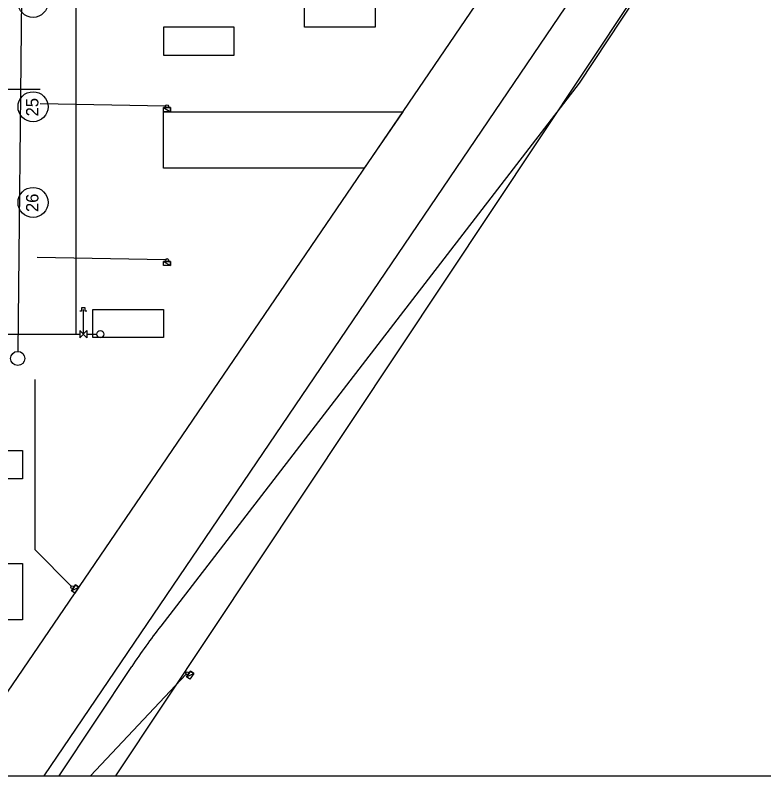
# Model space of a CAD drawing. Extents: x -264031 to -263588, y -1242281 to -1242059.
# Drawn here: x -263792.5 to -263739.4, y -1242281.4 to -1242227.5 of the extents above; entities that cross this region are included whole.
import ezdxf

# ---------------------------------------------------------------- set-up
doc = ezdxf.new("R2010")
doc.units = 0
for name, color, linetype in [('HESCON_OSI_STAVBY_KFA', 7, 'Continuous'), ('KFA_2D_SITUACIA_DSP', 7, 'Continuous'), ('KFA_JESTV_IS_DSP_-_KANAL_SPLASK', 7, 'Continuous'), ('RAM_NA_TLAC_3xA4_1-750', 7, 'Continuous')]:
    doc.layers.add(name, color=color, linetype=linetype)

msp = doc.modelspace()

# ---------------------------------------------------------------- linework, layer by layer
at = {"layer": 'HESCON_OSI_STAVBY_KFA'}
for centre in [(-263791.21, -1242226.632), (-263791.21, -1242234.032), (-263791.21, -1242240.807)]:
    msp.add_circle(centre, 1.064, dxfattribs=at)
at = {"layer": 'KFA_2D_SITUACIA_DSP'}
for p, q in [((-263788.143, -1242250.14), (-263788.143, -1242082.64)), ((-263785.333, -1242281.427), (-263734.49, -1242204.937)), ((-263790.417, -1242281.427), (-263742.736, -1242211.145)), ((-263797.061, -1242281.427), (-263751.864, -1242215.081)), ((-263743.421, -1242218.608), (-263752.521, -1242232.37)), ((-263781.968, -1242228.382), (-263781.968, -1242230.382)), ((-263776.968, -1242228.382), (-263781.968, -1242228.382)), ((-263776.968, -1242230.382), (-263776.968, -1242228.382)), ((-263781.968, -1242230.382), (-263776.968, -1242230.382)), ((-263798.041, -1242232.793), (-263790.695, -1242232.793)), ((-263752.521, -1242232.37), (-263782.166, -1242270.821)), ((-263781.818, -1242233.99), (-263790.714, -1242233.827)), ((-263781.968, -1242234.092), (-263781.468, -1242234.092)), ((-263781.968, -1242234.382), (-263781.968, -1242234.092)), ((-263781.968, -1242234.092), (-263781.468, -1242234.382)), ((-263781.968, -1242234.092), (-263781.468, -1242234.382)), ((-263781.468, -1242234.092), (-263781.968, -1242234.092)), ((-263781.468, -1242234.382), (-263781.968, -1242234.382)), ((-263781.968, -1242234.382), (-263771.968, -1242234.382)), ((-263781.968, -1242238.382), (-263781.968, -1242234.382)), ((-263781.968, -1242234.382), (-263781.968, -1242234.382)), ((-263781.468, -1242234.092), (-263781.468, -1242234.382)), ((-263781.468, -1242234.382), (-263781.468, -1242234.092)), ((-263771.968, -1242234.382), (-263765.013, -1242234.382)), ((-263765.013, -1242234.382), (-263767.738, -1242238.382)), ((-263771.968, -1242238.382), (-263781.968, -1242238.382)), ((-263767.738, -1242238.382), (-263771.968, -1242238.382)), ((-263781.818, -1242244.885), (-263790.914, -1242244.718)), ((-263781.968, -1242244.987), (-263781.468, -1242244.987)), ((-263781.968, -1242245.277), (-263781.968, -1242244.987)), ((-263781.968, -1242244.987), (-263781.468, -1242245.277)), ((-263781.968, -1242244.987), (-263781.468, -1242245.277)), ((-263781.468, -1242244.987), (-263781.968, -1242244.987)), ((-263781.468, -1242244.987), (-263781.468, -1242245.277)), ((-263781.468, -1242245.277), (-263781.468, -1242244.987)), ((-263781.468, -1242245.277), (-263781.968, -1242245.277)), ((-263787.768, -1242248.265), (-263787.768, -1242248.515)), ((-263787.518, -1242248.265), (-263787.768, -1242248.265)), ((-263787.643, -1242250.14), (-263787.643, -1242248.39)), ((-263787.518, -1242248.515), (-263787.518, -1242248.265)), ((-263787.768, -1242248.515), (-263787.893, -1242248.515)), ((-263787.393, -1242248.515), (-263787.518, -1242248.515)), ((-263787.893, -1242250.39), (-263787.393, -1242249.89)), ((-263787.893, -1242249.89), (-263787.893, -1242250.39)), ((-263787.393, -1242250.39), (-263787.893, -1242249.89)), ((-263787.393, -1242249.89), (-263787.393, -1242250.39)), ((-263924.143, -1242250.14), (-263788.143, -1242250.14)), ((-263788.143, -1242250.14), (-263787.893, -1242250.14)), ((-263788.143, -1242250.14), (-263787.893, -1242250.14)), ((-263787.393, -1242250.14), (-263786.693, -1242250.14)), ((-263791.063, -1242265.427), (-263791.063, -1242253.362)), ((-263788.502, -1242267.989), (-263791.063, -1242265.427)), ((-263788.491, -1242268.322), (-263788.207, -1242267.91)), ((-263788.207, -1242267.91), (-263788.491, -1242268.322)), ((-263788.491, -1242268.322), (-263787.968, -1242268.075)), ((-263788.491, -1242268.322), (-263787.968, -1242268.075)), ((-263788.252, -1242268.487), (-263788.491, -1242268.322)), ((-263787.968, -1242268.075), (-263788.252, -1242268.487)), ((-263788.207, -1242267.91), (-263787.968, -1242268.075)), ((-263787.968, -1242268.075), (-263788.207, -1242267.91)), ((-263789.361, -1242281.427), (-263784.214, -1242273.68)), ((-263780.353, -1242274.236), (-263787.141, -1242281.427)), ((-263780.34, -1242274.426), (-263780.062, -1242274.011)), ((-263780.062, -1242274.011), (-263780.34, -1242274.426)), ((-263780.34, -1242274.426), (-263779.821, -1242274.173)), ((-263780.34, -1242274.426), (-263779.821, -1242274.173)), ((-263779.821, -1242274.173), (-263780.099, -1242274.588)), ((-263780.062, -1242274.011), (-263779.821, -1242274.173)), ((-263779.821, -1242274.173), (-263780.062, -1242274.011)), ((-263780.099, -1242274.588), (-263780.34, -1242274.426))]:
    msp.add_line(p, q, dxfattribs=at)
for points in [[(-263771.968, -1242224.382), (-263766.968, -1242224.382), (-263766.968, -1242228.382), (-263771.968, -1242228.382)], [(-263786.968, -1242248.382), (-263781.968, -1242248.382), (-263781.968, -1242250.382), (-263786.968, -1242250.382)]]:
    msp.add_lwpolyline(points, close=True, dxfattribs=at)
msp.add_lwpolyline([(-263802.068, -1242265.987), (-263799.468, -1242265.987), (-263799.468, -1242258.382), (-263791.968, -1242258.382), (-263791.968, -1242260.382), (-263796.968, -1242260.382), (-263796.968, -1242266.382), (-263791.968, -1242266.382), (-263791.968, -1242270.382), (-263799.468, -1242270.382), (-263799.468, -1242274.382), (-263796.968, -1242274.382), (-263796.968, -1242278.382), (-263794.987, -1242278.383), (-263797.069, -1242281.427)], dxfattribs=at)
for centre, radius in [((-263781.718, -1242233.992), 0.1), ((-263781.718, -1242244.887), 0.1), ((-263786.443, -1242250.14), 0.25), ((-263788.431, -1242268.059), 0.1), ((-263780.284, -1242274.163), 0.1)]:
    msp.add_circle(centre, radius, dxfattribs=at)
msp.add_arc((-263742.568, -1242301.35), 50, 142.3688, 146.3992, dxfattribs=at)
at = {"layer": 'KFA_JESTV_IS_DSP_-_KANAL_SPLASK'}
msp.add_line((-263791.929, -1242215.473), (-263792.293, -1242251.359), dxfattribs=at)
msp.add_circle((-263792.298, -1242251.859), 0.5, dxfattribs=at)
at = {"layer": 'RAM_NA_TLAC_3xA4_1-750'}
msp.add_lwpolyline([(-264030.986, -1242281.427), (-263873.486, -1242281.427), (-263730.986, -1242281.427), (-263588.486, -1242281.427), (-263588.486, -1242058.677), (-263730.986, -1242058.677), (-263873.486, -1242058.677), (-264030.986, -1242058.677)], close=True, dxfattribs=at)

# ---------------------------------------------------------------- texts
at = {"layer": 'HESCON_OSI_STAVBY_KFA'}
for s, p in [('25', (-263790.829, -1242234.712)), ('26', (-263790.829, -1242241.487))]:
    msp.add_text(s, height=0.875, rotation=90, dxfattribs=at).set_placement(p)

doc.saveas('drawing.dxf')
